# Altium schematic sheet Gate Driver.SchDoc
size 431 x 279 mm; Organization: ORGANIZATION; Address1: ADDRESS 1; Address2: ADDRESS 2; Address3: ADDRESS 3; Address4: ADDRESS 4; Revision: -; ENG_APP_DATE: --/--/--; DSN_APP_DATE: --/--/--; CHK_APP_DATE: --/--/--
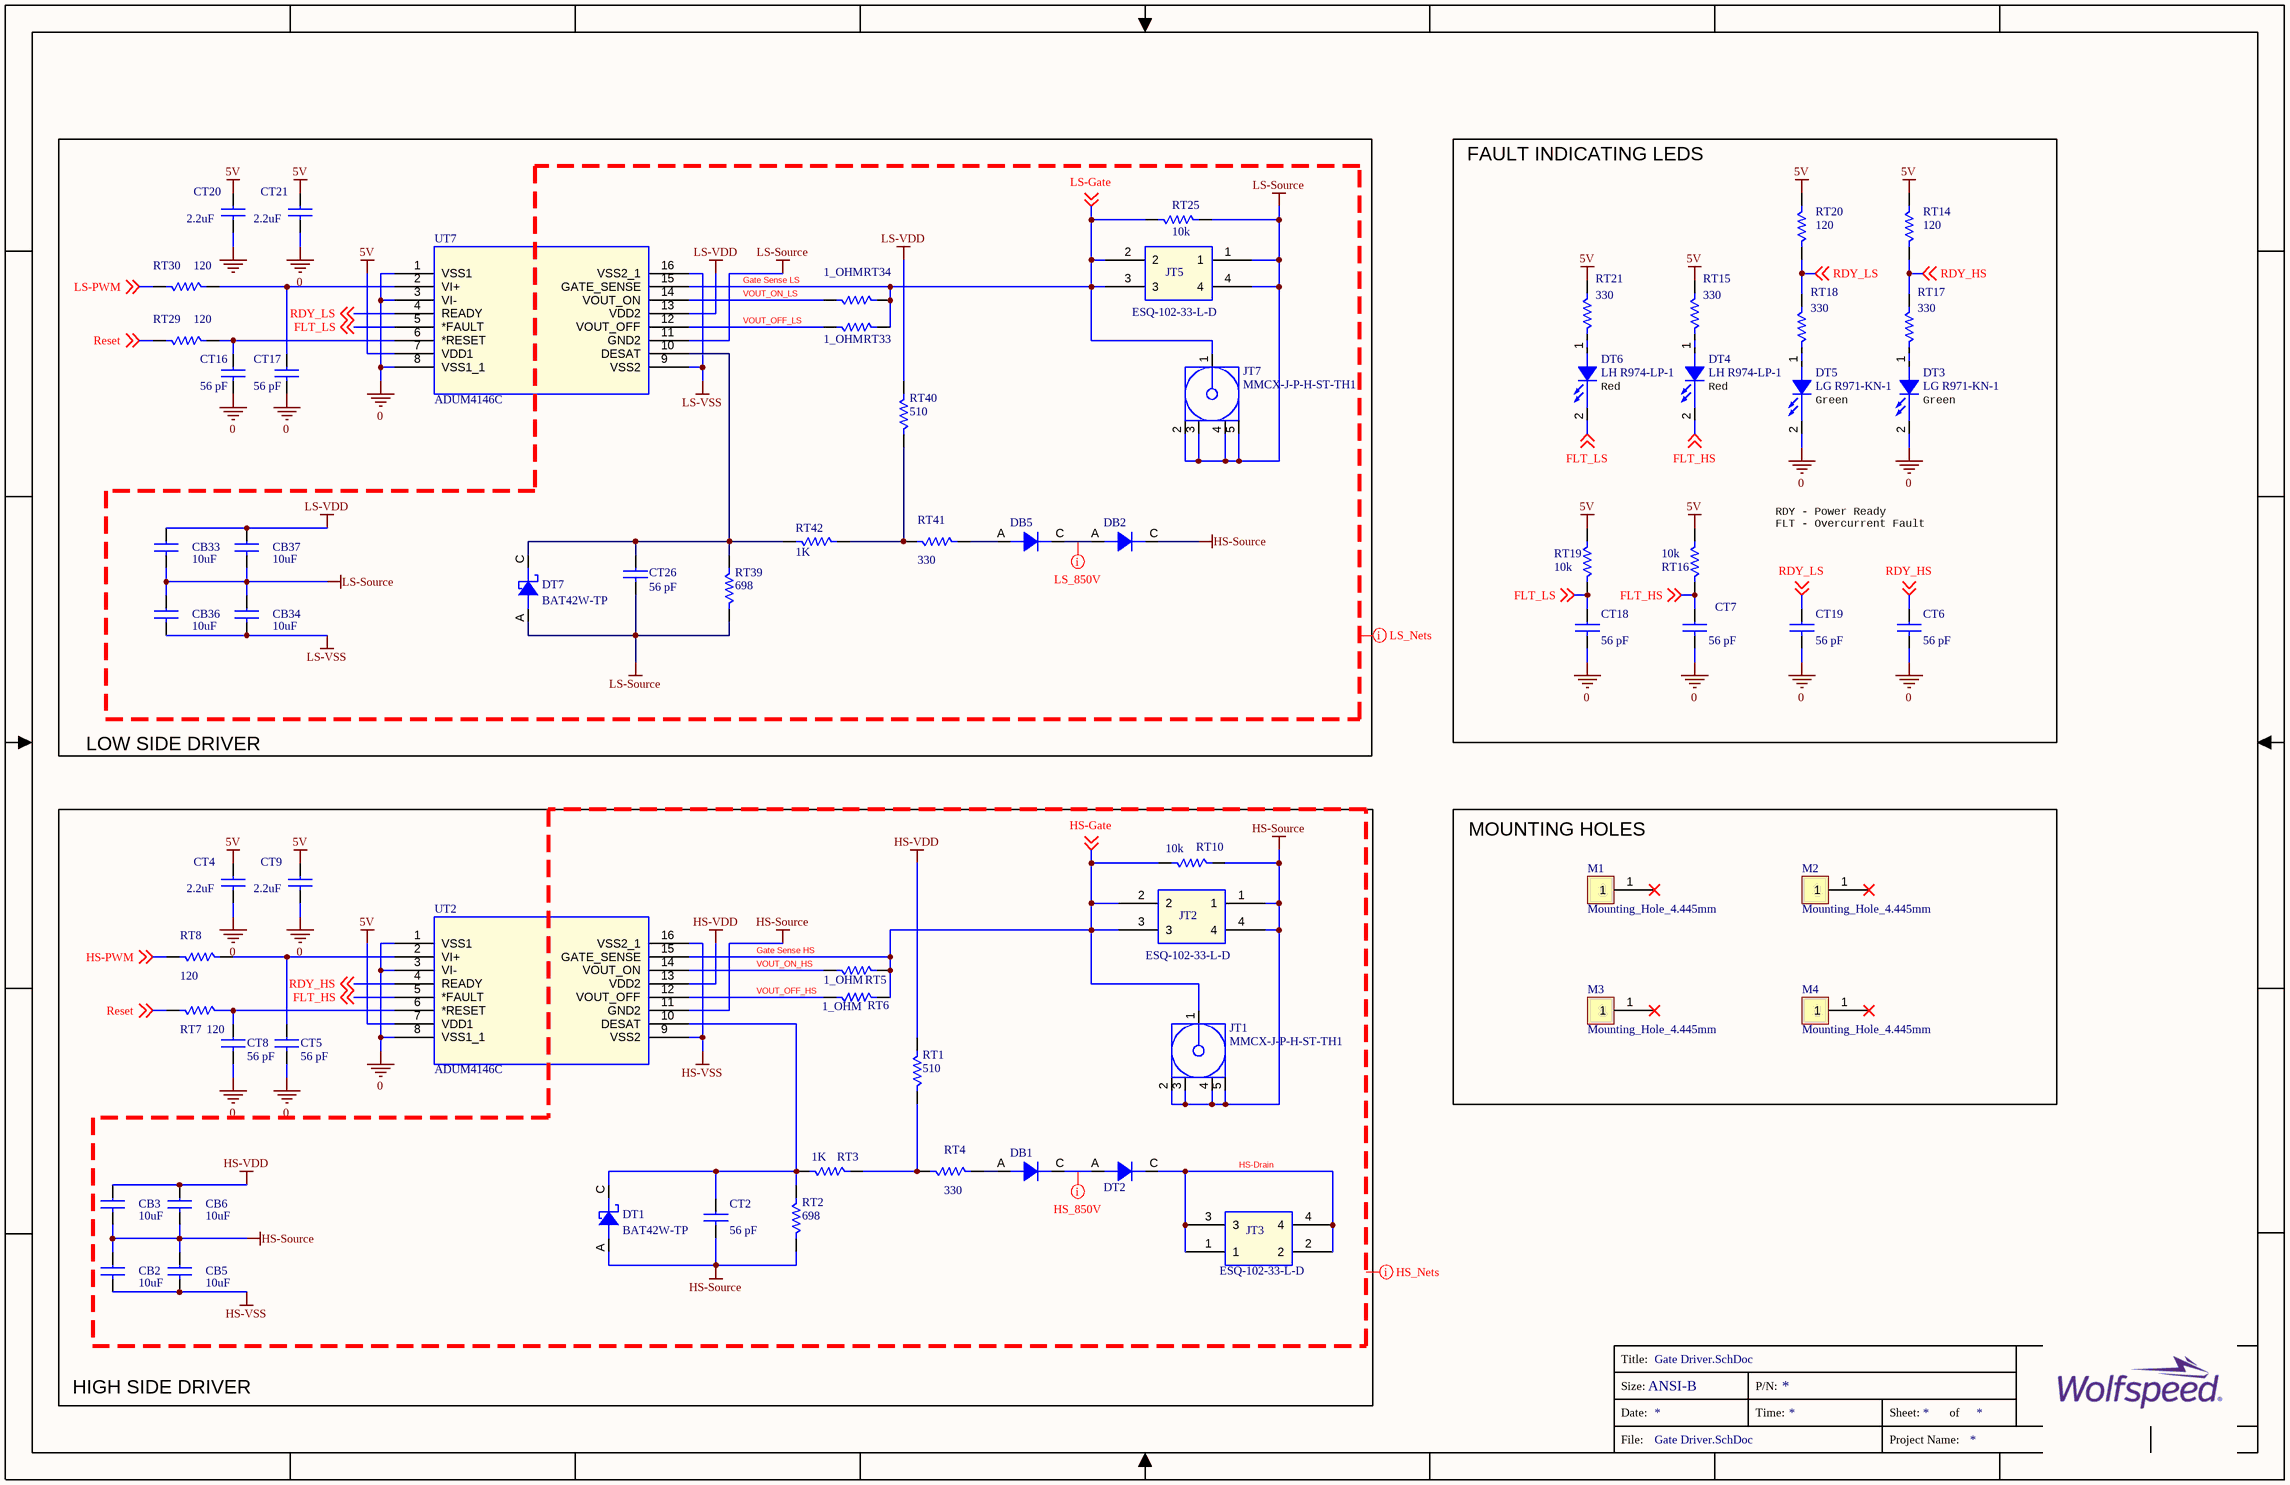
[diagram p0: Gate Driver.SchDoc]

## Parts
CB2  10uF  [C_1206]
CB3  10uF  [C_1206]
CB5  10uF  [C_1206]
CB6  10uF  [C_1206]
CB33  10uF  [C_1206]
CB34  10uF  [C_1206]
CB36  10uF  [C_1206]
CB37  10uF  [C_1206]
CT2  56 pF  [CAPC1608X90N]
CT4  2.2uF  [CAPC1608X90N]
CT5  56 pF  [CAPC1608X90N]
CT6  56 pF  [CAPC1608X90N]
CT7  56 pF  [CAPC1608X90N]
CT8  56 pF  [CAPC1608X90N]
CT9  2.2uF  [CAPC1608X90N]
CT16  56 pF  [CAPC1608X90N]
CT17  56 pF  [CAPC1608X90N]
CT18  56 pF  [CAPC1608X90N]
CT19  56 pF  [CAPC1608X90N]
CT20  2.2uF  [CAPC1608X90N]
CT21  2.2uF  [CAPC1608X90N]
CT26  56 pF  [CAPC1608X90N]
DB1  US3M-13  [DO-214AB-SMC]  (value not drawn)
DB2  US3M-13  [DO-214AB-SMC]  (value not drawn)
DB5  US3M-13  [DO-214AB-SMC]  (value not drawn)
DT1  BAT42W-TP  [sod123]
DT2  US3M-13  [DO-214AB-SMC]  (value not drawn)
DT3  LG R971-KN-1  [D_0805]
DT4  LH R974-LP-1  [D_0805]
DT5  LG R971-KN-1  [D_0805]
DT6  LH R974-LP-1  [D_0805]
DT7  BAT42W-TP  [sod123]
JT1  MMCX-J-P-H-ST-TH1  [MMCX-J-P-H-ST-TH1_PCB]
JT2  ESQ-102-33-L-D  [CON_2x2_100mil_TH]
JT3  ESQ-102-33-L-D  [CON_2x2_100mil_TH]
JT5  ESQ-102-33-L-D  [CON_2x2_100mil_TH]
JT7  MMCX-J-P-H-ST-TH1  [MMCX-J-P-H-ST-TH1_PCB]
M1  Mounting_Hole_4.445mm  [Mounting_Hole]
M2  Mounting_Hole_4.445mm  [Mounting_Hole]
M3  Mounting_Hole_4.445mm  [Mounting_Hole]
M4  Mounting_Hole_4.445mm  [Mounting_Hole]
RT1  510  [RESC2012X06N_510_698]
RT2  698  [RESC2012X06N_510_698]
RT3  1K  [RESC1608X55N]
RT4  330  [RESC1608X55N]
RT5  1_OHM  [RESC6432X70N]
RT6  1_OHM  [RESC6432X70N]
RT7  120  [RESC1608X55N]
RT8  120  [RESC1608X55N]
RT10  10k  [RESC1608X55N]
RT14  120  [RESC1608X55N]
RT15  330  [RESC1608X55N]
RT16  10k  [RESC1608X55N]
RT17  330  [RESC1608X55N]
RT18  330  [RESC1608X55N]
RT19  10k  [RESC1608X55N]
RT20  120  [RESC1608X55N]
RT21  330  [RESC1608X55N]
RT25  10k  [RESC1608X55N]
RT29  120  [RESC1608X55N]
RT30  120  [RESC1608X55N]
RT33  1_OHM  [RESC6432X70N]
RT34  1_OHM  [RESC6432X70N]
RT39  698  [RESC2012X06N_510_698]
RT40  510  [RESC2012X06N_510_698]
RT41  330  [RESC1608X55N]
RT42  1K  [RESC1608X55N]
UT2  ADUM4146C  [SOIC127P1032X265-16N]
UT7  ADUM4146C  [SOIC127P1032X265-16N]

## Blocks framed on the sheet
LOW SIDE DRIVER: CB33 CB34 CB36 CB37 CT16 CT17 CT20 CT21 CT26 DB2 DB5 DT7 JT5 JT7 RT25 RT29 RT30 RT33 RT34 RT39-RT42 UT7
FAULT INDICATING LEDS: CT6 CT7 CT18 CT19 DT3-DT6 RT14-RT21
HIGH SIDE DRIVER: CB2 CB3 CB5 CB6 CT2 CT4 CT5 CT8 CT9 DB1 DT1 DT2 JT1-JT3 RT1-RT8 RT10 UT2
MOUNTING HOLES: M1-M4

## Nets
0: CT4.2 CT5.2 CT6.2 CT7.2 CT8.2 CT9.2 CT16.2 CT17.2 CT18.2 CT19.2 CT20.2 CT21.2 DT3.2(C) DT5.2(C) UT2.1(VSS1) UT2.3(VI-) UT2.8(VSS1_1) UT7.1(VSS1) UT7.3(VI-) UT7.8(VSS1_1)
5V: CT4.1 CT9.1 CT20.1 CT21.1 RT14.1 RT15.2 RT16.1 RT19.1 RT20.1 RT21.2 UT2.7(VDD1) UT7.7(VDD1)
HS-Source: CB2.1 CB3.2 CB5.1 CB6.2 CT2.2 DB2.C(CATHODE) DT1.A JT1.2(GND) JT1.3(GND) JT1.4(GND) JT1.5(GND) JT2.1 JT2.4 RT2.2 RT10.2 UT2.11(GND2)
HS-VDD: CB3.1 CB6.1 RT1.1 UT2.13(VDD2)
HS-VSS: CB2.2 CB5.2 UT2.9(VSS2) UT2.16(VSS2_1)
LS-Source: CB33.2 CB34.1 CB36.1 CB37.2 CT26.2 DT7.A JT5.1 JT5.4 JT7.2(GND) JT7.3(GND) JT7.4(GND) JT7.5(GND) RT25.2 RT39.2 UT7.11(GND2)
LS-VDD: CB33.1 CB37.1 RT40.1 UT7.13(VDD2)
LS-VSS: CB34.2 CB36.2 UT7.9(VSS2) UT7.16(VSS2_1)
FLT_HS: CT7.1 DT4.2(C) RT16.2 UT2.5(*FAULT) ; off-sheet FLT_HS
FLT_LS: CT18.1 DT6.2(C) RT19.2 UT7.5(*FAULT) ; off-sheet FLT_LS
Gate Sense HS: JT1.1(SIGNAL) JT2.2 JT2.3 RT5.2 RT6.2 RT10.1 UT2.15(GATE_SENSE) ; off-sheet HS-Gate  [also labelled HS-Gate]
Gate Sense LS: JT5.2 JT5.3 JT7.1(SIGNAL) RT25.1 RT33.2 RT34.2 UT7.15(GATE_SENSE) ; off-sheet LS-Gate  [also labelled LS-Gate]
HS-Drain: DT2.C(CATHODE) JT3.1 JT3.2 JT3.3 JT3.4
HS-PWM: RT8.1 ; off-sheet HS-PWM
LS-PWM: RT30.1 ; off-sheet LS-PWM
RDY_HS: CT6.1 RT14.2 RT17.2 UT2.4(READY) ; off-sheet RDY_HS
RDY_LS: CT19.1 RT18.2 RT20.2 UT7.4(READY) ; off-sheet RDY_LS
Reset: RT7.1 RT29.1 ; off-sheet Reset
VOUT_OFF_HS: RT6.1 UT2.12(VOUT_OFF)
VOUT_OFF_LS: RT33.1 UT7.12(VOUT_OFF)
VOUT_ON_HS: RT5.1 UT2.14(VOUT_ON)
VOUT_ON_LS: RT34.1 UT7.14(VOUT_ON)
NetCT2_1: CT2.1 DT1.C RT2.1 RT3.2 UT2.10(DESAT)
NetCT5_1: CT5.1 RT8.2 UT2.2(VI+)
NetCT8_1: CT8.1 RT7.2 UT2.6(*RESET)
NetCT16_1: CT16.1 RT29.2 UT7.6(*RESET)
NetCT17_1: CT17.1 RT30.2 UT7.2(VI+)
NetCT26_1: CT26.1 DT7.C RT39.1 RT42.2 UT7.10(DESAT)
NetDB1_A: DB1.A(ANODE) RT4.1
NetDB1_C: DB1.C(CATHODE) DT2.A(ANODE)
NetDB2_A: DB2.A(ANODE) DB5.C(CATHODE)
NetDB5_A: DB5.A(ANODE) RT41.1
NetDT3_1: DT3.1(A) RT17.1
NetDT4_1: DT4.1(A) RT15.1
NetDT5_1: DT5.1(A) RT18.1
NetDT6_1: DT6.1(A) RT21.1
NetRT1_2: RT1.2 RT3.1 RT4.2
NetRT40_2: RT40.2 RT41.2 RT42.1

Not connected (* = marked no-connect by the designer): M1 1*; M2 1*; M3 1*; M4 1*

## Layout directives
net class LS_Nets: 0, 5V, FLT_LS, Gate Sense LS, HS-Source, LS-Gate, LS-PWM, LS-Source, LS-VDD, LS-VSS, RDY_LS, Reset, VOUT_OFF_LS, VOUT_ON_LS
net class HS_Nets: 0, 5V, FLT_HS, Gate Sense HS, HS-Drain, HS-Gate, HS-PWM, HS-Source, HS-VDD, HS-VSS, RDY_HS, Reset, VOUT_OFF_HS, VOUT_ON_HS
net class LS_850V: NetDB2_A
net class HS_850V: NetDB1_C

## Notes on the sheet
- (near DT6) Red
- (near DT4) Red
- (near DT5) Green
- (near DT3) Green
- RDY - Power Ready
  FLT - Overcurrent Fault

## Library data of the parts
CB2 CB3 CB33 CB36 = CAP_10uF: CAP CER 10UF 16V X7R 1206; Company Part Status: New; PART_NUMBER: TMP-885; Manufacturer: Murata Electronics North America; Manufacturer PN: GCM31CR71C106KA64L; Dielectric Type: Capacitors; Tolerance: 10%; CLASS: DISCRETE
CB5 CB6 CB34 CB37 = CAP_10uF: CAP CER 10UF 16V X7R 1206; Company Part Status: New; Manufacturer PN: GCM31CR71C106KA64L; Manufacturer: Murata Electronics North America; PART_NUMBER: TMP-885; CLASS: DISCRETE; Tolerance: 10%; Dielectric Type: Capacitors
CT2 CT5 CT6 CT8 CT17 CT19 CT26 = CAP_Dup1: CAP CER 56PF 50V C0G/NP0 0603; Manufacturer PN: CL10C560JB8NNNC; Manufacturer: Samsung Electro-Mechanics; CLASS: DISCRETE; Tolerance: 5%; Temperature Coefficient: C0G, NP0; Dielectric Type: Capacitors
CT4 CT9 CT20 CT21 = CAP_2.2uF: CAP CER 2.2UF 50V X5R 0603; Company Part Status: Obsolete; Manufacturer: Murata Electronics North America; Manufacturer PN: GRT188R61H225ME13D; Tolerance: 20%; CLASS: DISCRETE
CT7 CT16 CT18 = CAP_Dup1: CAP CER 56PF 50V C0G/NP0 0603; Manufacturer: Samsung Electro-Mechanics; Manufacturer PN: CL10C560JB8NNNC; Dielectric Type: Capacitors; Temperature Coefficient: C0G, NP0; Tolerance: 5%; CLASS: DISCRETE
DB1 DB2 DB5 = US3M-13: DIODE GEN PURP 1KV 3A SMC; Manufacturer: Diodes; Average Rectified Current: 1A; Reverse Recovery Time: 75ns; Element Configuration: Single; Max Forward Surge Current (Ifsm): 30A; Description: VR=1000V IF=3A 25pF Trr=70ns
DT1 DT7 = DIODE_SCHOTTKY_11: DIODE SCHOTTKY 30V 200MA SOD123; Company Part Status: Released; Manufacturer: Micro Commercial Co; CLASS: DISCRETE
DT2 = US3M-13_TOP: DIODE GEN PURP 1KV 3A SMC; Average Rectified Current: 1A; Reverse Recovery Time: 75ns; Element Configuration: Single; Max Forward Surge Current (Ifsm): 30A; Description: VR=1000V IF=3A 25pF Trr=70ns
DT3 = LED: LED GREEN DIFFUSED 0805 SMD; PART_NUMBER: TMP-915; Manufacturer: OSRAM Opto Semiconductors Inc.; Rated Voltage: 2.2V; CLASS: DISCRETE
DT4 DT6 = LED_1: LED RED DIFFUSED 0805 SMD; Manufacturer: OSRAM Opto Semiconductors Inc.; PART_NUMBER: TMP-917; CLASS: DISCRETE; Rated Voltage: 1.8V @ 20mA
DT5 = LED: LED GREEN DIFFUSED 0805 SMD; Manufacturer: OSRAM Opto Semiconductors Inc.; PART_NUMBER: TMP-915; CLASS: DISCRETE; Rated Voltage: 2.2V
JT1 JT7 = MMCX-J-P-H-ST-TH1: CONN MMCX JACK STR 50 OHM PCB; Manufacturer: Samtec; Body Plating: Gold; Body Material: Brass; Frequency: 6Hz; Impedance: 50R; Operating Frequency: 0 to 6Hz
JT2 JT5 = CON_2x2_100mil_NEW: Conn Elevated Socket SKT 4 POS 2.54mm Solder ST Thru-Hole; Manufacturer: Samtec; CLASS: IO; Number of Contacts: 4; Gender: Receptacle
JT3 = CON_2x2_100mil: Conn Elevated Socket SKT 4 POS 2.54mm Solder ST Thru-Hole; Manufacturer: Samtec; CLASS: IO; Number of Contacts: 4; Gender: Receptacle
RT1 = RES_7: RES SMD 510 OHM 1% 0.4W 0805; Manufacturer: Vishay Dale; Manufacturer Part Number: RCS0805510RFKEA; Resistance: 510R; Max Power Dissipation: 400mW; Temperature Coefficient: 100ppm/°C; Parameter 1: HS_Components
RT2 RT39 = RES_8: RES 698 OHM 1% 1/8W 0805; Manufacturer: Stackpole Electronics; Manufacturer Part Number: RMCF0805FT698R; Resistance: 698R; Max Power Dissipation: 125mW; Temperature Coefficient: 100ppm/°C
RT3 RT42 = RES_6: RES 1K OHM 1% 1/8W 0603; Manufacturer: Stackpole Electronics; Manufacturer Part Number: RNCP0603FTD1K00; Resistance: 1kR; Max Power Dissipation: 125mW; Temperature Coefficient: 100ppm/°C
RT4 RT17 RT21 RT41 = RES_3: RES SMD 330 OHM 5% 1/10W 0603; Manufacturer PN: RC0603JR-07330RL; Manufacturer: Yageo; Company Part Status: Released; CLASS: DISCRETE; Rated Power: 0.1W, 1/10W; Temperature Coefficient: 100ppm/C
RT5 RT6 = RES_4: RES SMD 1 OHM 1% 1.5W 2512; Company Part Status: Released; Manufacturer: Vishay Dale; Manufacturer PN: CRCW25121R00FKEGHP; Temperature Coefficient: 100ppm/C; CLASS: DISCRETE
RT7 RT8 RT14 RT20 RT29 RT30 = RES_1: RES SMD 120 OHM 1% 1/10W 0603; PART_NUMBER: TMP-957; Company Part Status: Released; Manufacturer: Yageo; Manufacturer PN: RC0603FR-07120RL; Temperature Coefficient: 100ppm/C; Rated Power: 0.1W, 1/10W; CLASS: DISCRETE
RT10 RT16 RT19 RT25 = RES: RES SMD 10K OHM 1% 1/10W 0603; Manufacturer PN: ERJ-3EKF1002V; Manufacturer: Panasonic Electronic Components; Company Part Status: New; PART_NUMBER: TMP-788; CLASS: DISCRETE; Rated Power: 0.1W, 1/10W; Temperature Coefficient: 100ppm/C
RT15 RT18 = RES_3: RES SMD 330 OHM 5% 1/10W 0603; Company Part Status: Released; Manufacturer: Yageo; Manufacturer PN: RC0603JR-07330RL; Temperature Coefficient: 100ppm/C; Rated Power: 0.1W, 1/10W; CLASS: DISCRETE
RT33 RT34 = RES_4: RES SMD 1 OHM 1% 1.5W 2512; Manufacturer PN: CRCW25121R00FKEGHP; Manufacturer: Vishay Dale; Company Part Status: Released; CLASS: DISCRETE; Temperature Coefficient: 100ppm/C
RT40 = RES_7: RES SMD 510 OHM 1% 0.4W 0805; Manufacturer: Vishay Dale; Manufacturer Part Number: RCS0805510RFKEA; Resistance: 510R; Max Power Dissipation: 400mW; Temperature Coefficient: 100ppm/°C
UT2 UT7 = ADUM4146C: 1500V ISOLATED HI UVLO 14.5V GAT; Manufacturer: Analog Devices; Manufacturer Part Number: ADUM4146CRWZ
